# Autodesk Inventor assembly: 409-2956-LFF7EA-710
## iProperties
Created: 2010-06
Part Number: 409-2956-LFF7EA-710
Document SubType Name: Weldment
Designer: S. Boerckel
Mass: 42975.8 g
Surface Area: 14244.3 cm^2
Volume: 5442.6 cm^3
Density: 7.89619 g/cm^3
Description: STRAINER DISCHARGE SPOOL
Weld Material: Welded Steel Mild
User Status: WELD
Material: WELDMENT
SMR: =<MATERIAL>
Author: S. Boerckel
Revision Number: B
Subject: DEMIN WATER FORWARDING PUMP SKID-7EA
